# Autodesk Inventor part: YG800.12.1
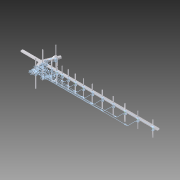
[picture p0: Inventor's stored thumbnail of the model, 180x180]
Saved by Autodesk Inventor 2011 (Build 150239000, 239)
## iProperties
Created: 2014-03
Part Number: YG800.12.1
Document SubType Name: Modeling
Designer: Evgeny
Density: 1 g/cm^3
Author: Evgeny
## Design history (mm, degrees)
sketch "Эскиз1"
  geometry: C1 r 4 at (0, 0); C2 r 3 at (0, 0); C3 r 4 at (80, 0); C4 r 3 at (80, 0); C5 r 4 at (125, 0); C6 r 3 at (125, 0); C7 r 4 at (172, 0); C8 r 3 at (172, 0); C9 r 4 at (226, 0); C10 r 3 at (226, 0); C11 r 4 at (288.5, 0); C12 r 3 at (288.5, 0); C13 r 4 at (359.5, 0); C14 r 3 at (359.5, 0); C15 r 4 at (438.5, 0); C16 r 3 at (438.5, 0); C17 r 4 at (525.5, 0); C18 r 3 at (525.5, 0); C19 r 4 at (725.5, 0); C20 r 3 at (725.5, 0); C21 r 4 at (621.5, 0); C22 r 3 at (621.5, 0); C23 r 4 at (21.5, 95); C24 r 3 at (21.5, 95); C25 r 4 at (35, -95); C26 r 3 at (35, -95); C27 r 3 at (837.5, 0); C28 r 4 at (837.5, 0); C29 r 3 at (969, 0); C30 r 4 at (969, 0); 1 further point
  constraints: 30 centre point, 16 coincident
  dimensions: "d0" = 8 diameter of C1; "d1" = 6 diameter of C2; "d2" = 8 diameter of C3; "d3" = 6 diameter of C4; "d4" = 8 diameter of C5; "d5" = 6 diameter of C6; "d6" = 8 diameter of C7; "d7" = 6 diameter of C8; "d8" = 8 diameter of C9; "d9" = 6 diameter of C10; "d10" = 8 diameter of C11; "d11" = 6 diameter of C12; "d12" = 8 diameter of C13; "d13" = 6 diameter of C14; "d14" = 8 diameter of C15; "d15" = 6 diameter of C16; "d16" = 8 diameter of C17; "d17" = 6 diameter of C18; "d18" = 8 diameter of C19; "d19" = 6 diameter of C20; "d20" = 8 diameter of C21; "d21" = 6 diameter of C22; "d22" = 8 diameter of C23; "d23" = 6 diameter of C24; "d24" = 8 diameter of C25; "d25" = 6 diameter of C26; "d26" = 21.5 horizontal distance of point (0, 0) C23.centre; "d27" = 35 horizontal distance of C25.centre C1.centre; "d28" = 95 vertical distance of point (0, 0) C24.centre; "d29" = 95 vertical distance of point (0, 0) C25.centre; "d30" = 80 distance of C3.centre point (0, 0); "d31" = 125 distance of C5.centre point (0, 0); "d32" = 172 distance of C7.centre point (0, 0); "d33" = 226 distance of point (0, 0) C9.centre; "d34" = 288.5 distance of point (0, 0) C11.centre; "d35" = 359.5 distance of point (0, 0) C13.centre; "d36" = 438.5 distance of point (0, 0) C15.centre; "d37" = 525.5 distance of point (0, 0) C17.centre; "d38" = 621.5 distance of point (0, 0) C21.centre; "d39" = 725.5 distance of point (0, 0) C19.centre; "d40" = 8 diameter of C28; "d41" = 6 diameter of C27; "d42" = 8 diameter of C30; "d43" = 6 diameter of C29; "d46" = 837.5 distance of point (0, 0) C28.centre; "d47" = 969 distance of point (0, 0) C30.centre
extrude "Выдавливание2" join sketch "Эскиз1" stored distance "d50" = 159; taper "d51" = 0 deg
extrude "Выдавливание3" join sketch "Эскиз1" stored distance "d52" = 156.5; taper "d53" = 0 deg
extrude "Выдавливание4" join sketch "Эскиз1" stored distance "d54" = 154; taper "d55" = 0 deg
extrude "Выдавливание5" join sketch "Эскиз1" stored distance "d56" = 151.5; taper "d57" = 0 deg
extrude "Выдавливание6" join sketch "Эскиз1" stored distance "d58" = 149; taper "d59" = 0 deg
extrude "Выдавливание7" join sketch "Эскиз1" stored distance "d60" = 146; taper "d61" = 0 deg
extrude "Выдавливание8" join sketch "Эскиз1" stored distance "d62" = 144; taper "d63" = 0 deg
extrude "Выдавливание9" join sketch "Эскиз1" stored distance "d64" = 141; taper "d65" = 0 deg
extrude "Выдавливание10" join sketch "Эскиз1" stored distance "d66" = 138; taper "d67" = 0 deg
extrude "Выдавливание11" join sketch "Эскиз1" stored distance "d68" = 135; taper "d69" = 0 deg
extrude "Выдавливание12" join sketch "Эскиз1" stored distance "d70" = 133; taper "d71" = 0 deg
node "РабПлоскость1"
sketch "Эскиз2"
  geometry: L1 (0.073, 69)-(0.073, -69); L2 (50.073, -69)-(50.073, -7); L3 (50.073, 69)-(50.073, 7); A1 r 25 centre (25.073, 69) between (50.073, 69) and (0.073, 69); A2 r 25 centre (25.073, -69) between (0.073, -69) and (50.073, -69); 1 further point
  constraints: 6 end point, 4 point on circle, 3 tangent, 2 centre point, 1 collinear, 1 parallel, 1 vertical
  dimensions: "d83" = 50 diameter of A1; "d84" = 50 diameter of A2; "d85" = 69 vertical distance of point (0, 0) A1.centre; "d86" = 138 distance of A2.centre A1.centre; "d87" = 50 distance between parallel lines of L2 L1; "d88" = 7 vertical distance of L3.end point (0, 0); "d89" = 14 distance of L2.end L3.end
feature "Сдвиг1" sketch "Эскиз2" dims "d90" = 0
sketch "Эскиз4"
  geometry: L1 (7, 6.5)-(27, 6.5); L2 (27, 6.5)-(27, -6.5); L3 (27, -6.5)-(7, -6.5); L4 (7, -6.5)-(7, 6.5); L5 (26, 5.5)-(8, 5.5); L6 (8, 5.5)-(8, -5.5); L7 (8, -5.5)-(26, -5.5); L8 (26, -5.5)-(26, 5.5); 1 further point
  constraints: 16 end point, 4 parallel, 2 horizontal, 2 perpendicular
  dimensions: "d91" = 7 distance from line of L4 point (0, 0); "d92" = 20 distance between parallel lines of L2 L4; "d93" = 13 distance between parallel lines of L1 L3; "d94" = 6.5 distance from line of L3 point (0, 0); "d95" = 1 distance between parallel lines of L4 L6; "d96" = 1 distance between parallel lines of L1 L5; "d97" = 1 distance between parallel lines of L8 L2; "d98" = 1 distance between parallel lines of L3 L7
extrude "Выдавливание13" join sketch "Эскиз4" distance "d99" = 1000; taper "d101" = 0 deg; dims "d100" = 200, "d102" = 0
sketch "Эскиз5"
  geometry: C1 r 2 at (235, -5.5); C2 r 2 at (280, -5.5); C3 r 2 at (325, -5.5); C4 r 2 at (372, -5.5); C5 r 2 at (426, -5.5); C6 r 2 at (488.5, -5.5); C7 r 2 at (559.5, -5.5); C8 r 2 at (638.5, -5); C9 r 2 at (725.5, -5.5); C10 r 2 at (821.5, -5.5); C11 r 2 at (925.5, -5); C12 r 2 at (1037.5, -5.5); C13 r 2 at (1169, -5); C14 r 2 at (200, -5.5); 1 further point
  constraints: 14 centre point, 1 coincident
  dimensions: "d104" = 4 diameter of C1; "d105" = 4 diameter of C2; "d106" = 4 diameter of C3; "d107" = 4 diameter of C4; "d108" = 4 diameter of C5; "d109" = 4 diameter of C6; "d110" = 4 diameter of C7; "d111" = 4 diameter of C8; "d112" = 4 diameter of C9; "d113" = 4 diameter of C10; "d114" = 4 diameter of C11; "d115" = 4 diameter of C12; "d116" = 4 diameter of C13; "d117" = 35 distance of C1.centre point (200, -5.5); "d118" = 45 distance of C2.centre C1.centre; "d119" = 45 distance of C3.centre C2.centre; "d120" = 47 distance of C4.centre C3.centre; "d121" = 54 distance of C5.centre C4.centre; "d122" = 62.5 distance of C6.centre C5.centre; "d123" = 71 distance of C7.centre C6.centre; "d124" = 79 horizontal distance of C8.centre C7.centre; "d125" = 87 horizontal distance of C9.centre C8.centre; "d126" = 96 distance of C10.centre C9.centre; "d127" = 104 horizontal distance of C11.centre C10.centre; "d128" = 112 horizontal distance of C12.centre C11.centre; "d129" = 131.5 horizontal distance of C13.centre C12.centre; "d161" = 4 diameter of C14
sketch "Эскиз6"
  geometry: L1 (157, -9)-(212, 119.744); L2 (212, 119.744)-(230.392, 111.887); L3 (230.392, 111.887)-(178.749, -9); L4 (178.749, -9)-(230.392, -129.887); L5 (230.392, -129.887)-(212, -137.744); L6 (212, -137.744)-(157, -9); 1 further point
  constraints: 12 end point, 2 parallel, 2 perpendicular
  dimensions: "d132" = 55 horizontal distance of L1.end L1.start; "d133" = 140 distance of L1.start L1.end; "d134" = 20 distance between parallel lines of L3 L1; "d135" = 140 distance of L5.end L1.start; "d136" = 55 horizontal distance of L5.end L1.start; "d137" = 20 distance between parallel lines of L4 L6; "d138" = 43 horizontal distance of point (200, -26) L1.start
extrude "Выдавливание15" join sketch "Эскиз6" distance "d139" = 13; taper "d140" = 0 deg
extrude "Выдавливание18" join sketch "Эскиз5" distance "d162" = 14; taper "d163" = 0 deg
extrude "Выдавливание21" join sketch "Эскиз1" stored distance "d176" = 230; taper "d177" = 0 deg
sketch "Эскиз10"
  geometry: L1 (0, 0)-(13, 0) reference; C1 r 2 at (6.5, 6.5); 1 further point
  constraints: 1 centre point
  dimensions: "d178" = 4 diameter of C1; "d179" = 6.5 distance from line of C1.centre L1
extrude "Выдавливание22" join sketch "Эскиз10" distance "d180" = 14; taper "d181" = 0 deg
sketch "Эскиз11"
  geometry: L1 (0, 0)-(13, 0) reference; C1 r 2 at (7, -43); 1 further point
  constraints: 1 centre point
  dimensions: "d182" = 4 diameter of C1; "d183" = 43 distance from line of L1 C1.centre
extrude "Выдавливание23" join sketch "Эскиз11" distance "d184" = 14; taper "d185" = 0 deg
extrude "Выдавливание24" join sketch "Эскиз1" stored distance "d186" = 230; taper "d187" = 0 deg
node "Твердое тело1"
